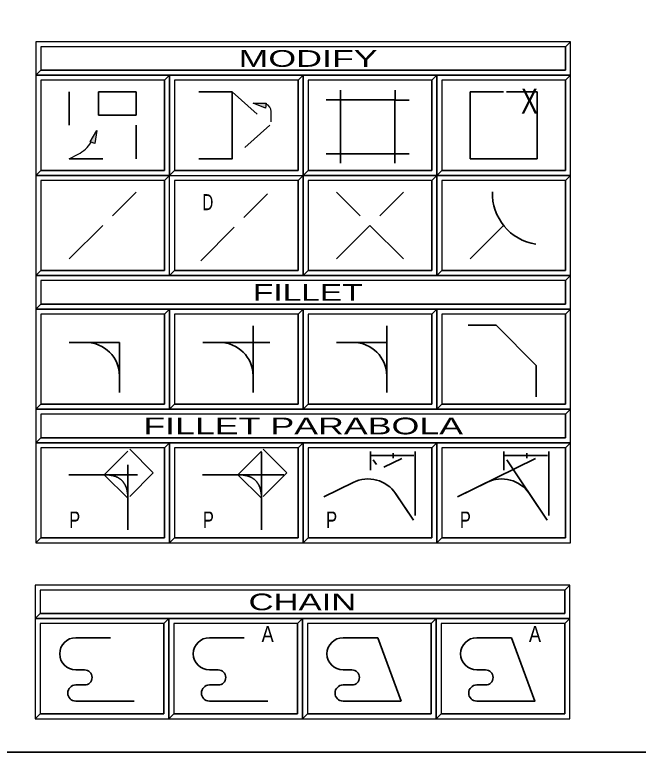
# Model space of a CAD drawing. Extents: x 95906.8 to 95923.6, y 90964.8 to 90972.8.
# Drawn here: x 95908.871 to 95910.737, y 90964.762 to 90966.969 of the extents above; entities that cross this region are included whole.
import ezdxf
from ezdxf.enums import TextEntityAlignment as Align

# ---------------------------------------------------------------- set-up
doc = ezdxf.new("R2010")
doc.units = 0
doc.header["$LTSCALE"] = 0.019
doc.linetypes.add('DOTTED', pattern=[1.5, 0.3, -1.2])
doc.linetypes.add('MEDIUM_DASHED', pattern=[4.5, 3, -1.5])
for name, color, linetype, lineweight in [('1', 7, 'Continuous', 25), ('11', 7, 'Continuous', 25), ('12', 7, 'Continuous', 25), ('18', 7, 'Continuous', 25), ('2', 7, 'Continuous', 13), ('3', 7, 'Continuous', 25), ('6', 7, 'Continuous', 35), ('7', 7, 'Continuous', 35)]:
    doc.layers.add(name, color=color, linetype=linetype, lineweight=lineweight)

msp = doc.modelspace()

# ---------------------------------------------------------------- hatches: boundary and pattern name
at = {"layer": '6'}
for points in [[(95909.5847, 90966.7042), (95909.6243, 90966.7047), (95909.6217, 90966.6895)], [(95909.1174, 90966.6228), (95909.1115, 90966.5841), (95909.097, 90966.5893)]]:
    msp.add_hatch(color=256, dxfattribs=at).paths.add_polyline_path(points)

# ---------------------------------------------------------------- linework, layer by layer
at = {"layer": '1'}
for points in [[(95908.9345, 90966.7883), (95910.5345, 90966.7883), (95910.5345, 90966.8883), (95908.9345, 90966.8883)], [(95908.9345, 90966.4883), (95909.3345, 90966.4883), (95909.3345, 90966.7883), (95908.9345, 90966.7883)], [(95909.3345, 90966.4883), (95909.7345, 90966.4883), (95909.7345, 90966.7883), (95909.3345, 90966.7883)], [(95909.7345, 90966.4883), (95910.1345, 90966.4883), (95910.1345, 90966.7883), (95909.7345, 90966.7883)], [(95910.1345, 90966.4883), (95910.5345, 90966.4883), (95910.5345, 90966.7883), (95910.1345, 90966.7883)], [(95908.9345, 90966.1883), (95909.3345, 90966.1883), (95909.3345, 90966.4883), (95908.9345, 90966.4883)], [(95909.7345, 90966.1883), (95910.1345, 90966.1883), (95910.1345, 90966.4883), (95909.7345, 90966.4883)], [(95910.1345, 90966.1883), (95910.5345, 90966.1883), (95910.5345, 90966.4883), (95910.1345, 90966.4883)], [(95908.9345, 90966.0883), (95910.5345, 90966.0883), (95910.5345, 90966.1883), (95908.9345, 90966.1883)], [(95908.9345, 90965.7883), (95909.3345, 90965.7883), (95909.3345, 90966.0883), (95908.9345, 90966.0883)], [(95909.3345, 90965.7883), (95909.7345, 90965.7883), (95909.7345, 90966.0883), (95909.3345, 90966.0883)], [(95909.7345, 90965.7883), (95910.1345, 90965.7883), (95910.1345, 90966.0883), (95909.7345, 90966.0883)], [(95910.1345, 90965.7883), (95910.5345, 90965.7883), (95910.5345, 90966.0883), (95910.1345, 90966.0883)], [(95908.9345, 90965.6883), (95910.5345, 90965.6883), (95910.5345, 90965.7883), (95908.9345, 90965.7883)], [(95908.9345, 90965.3883), (95909.3345, 90965.3883), (95909.3345, 90965.6883), (95908.9345, 90965.6883)], [(95909.3345, 90965.3883), (95909.7345, 90965.3883), (95909.7345, 90965.6883), (95909.3345, 90965.6883)], [(95909.7345, 90965.3883), (95910.1345, 90965.3883), (95910.1345, 90965.6883), (95909.7345, 90965.6883)], [(95910.1345, 90965.3883), (95910.5345, 90965.3883), (95910.5345, 90965.6883), (95910.1345, 90965.6883)], [(95908.9323, 90965.1617), (95910.5323, 90965.1617), (95910.5323, 90965.2617), (95908.9323, 90965.2617)], [(95908.9323, 90964.8617), (95909.3323, 90964.8617), (95909.3323, 90965.1617), (95908.9323, 90965.1617)], [(95909.3323, 90964.8617), (95909.7323, 90964.8617), (95909.7323, 90965.1617), (95909.3323, 90965.1617)], [(95909.7323, 90964.8617), (95910.1323, 90964.8617), (95910.1323, 90965.1617), (95909.7323, 90965.1617)], [(95910.1323, 90964.8617), (95910.5323, 90964.8617), (95910.5323, 90965.1617), (95910.1323, 90965.1617)]]:
    msp.add_lwpolyline(points, close=True, dxfattribs=at)
at = {"layer": '11'}
for points in [[(95909.3495, 90966.5033), (95909.7195, 90966.5033), (95909.7195, 90966.7733), (95909.3495, 90966.7733)], [(95909.7495, 90966.5033), (95910.1195, 90966.5033), (95910.1195, 90966.7733), (95909.7495, 90966.7733)], [(95910.1495, 90966.5033), (95910.5195, 90966.5033), (95910.5195, 90966.7733), (95910.1495, 90966.7733)], [(95909.3495, 90966.2033), (95909.7195, 90966.2033), (95909.7195, 90966.4733), (95909.3495, 90966.4733)], [(95909.7495, 90966.2033), (95910.1195, 90966.2033), (95910.1195, 90966.4733), (95909.7495, 90966.4733)], [(95910.1495, 90966.2033), (95910.5195, 90966.2033), (95910.5195, 90966.4733), (95910.1495, 90966.4733)], [(95909.3495, 90965.8033), (95909.7195, 90965.8033), (95909.7195, 90966.0733), (95909.3495, 90966.0733)], [(95909.7495, 90965.8033), (95910.1195, 90965.8033), (95910.1195, 90966.0733), (95909.7495, 90966.0733)], [(95910.1495, 90965.8033), (95910.5195, 90965.8033), (95910.5195, 90966.0733), (95910.1495, 90966.0733)], [(95908.9495, 90965.4033), (95909.3195, 90965.4033), (95909.3195, 90965.6733), (95908.9495, 90965.6733)], [(95909.3495, 90965.4033), (95909.7195, 90965.4033), (95909.7195, 90965.6733), (95909.3495, 90965.6733)], [(95909.7495, 90965.4033), (95910.1195, 90965.4033), (95910.1195, 90965.6733), (95909.7495, 90965.6733)], [(95910.1495, 90965.4033), (95910.5195, 90965.4033), (95910.5195, 90965.6733), (95910.1495, 90965.6733)], [(95909.3473, 90964.8767), (95909.7173, 90964.8767), (95909.7173, 90965.1467), (95909.3473, 90965.1467)], [(95909.7473, 90964.8767), (95910.1173, 90964.8767), (95910.1173, 90965.1467), (95909.7473, 90965.1467)], [(95910.1473, 90964.8767), (95910.5173, 90964.8767), (95910.5173, 90965.1467), (95910.1473, 90965.1467)]]:
    msp.add_lwpolyline(points, close=True, dxfattribs=at)
at = {"layer": '12'}
for points in [[(95908.9495, 90966.5033), (95909.3195, 90966.5033), (95909.3195, 90966.7733), (95908.9495, 90966.7733)], [(95908.9495, 90966.2033), (95909.3195, 90966.2033), (95909.3195, 90966.4733), (95908.9495, 90966.4733)], [(95908.9495, 90965.8033), (95909.3195, 90965.8033), (95909.3195, 90966.0733), (95908.9495, 90966.0733)], [(95908.9473, 90964.8767), (95909.3173, 90964.8767), (95909.3173, 90965.1467), (95908.9473, 90965.1467)]]:
    msp.add_lwpolyline(points, close=True, dxfattribs=at)
at = {"layer": '18'}
for points in [[(95908.9495, 90966.8033), (95910.5195, 90966.8033), (95910.5195, 90966.8733), (95908.9495, 90966.8733)], [(95908.9495, 90966.1033), (95910.5195, 90966.1033), (95910.5195, 90966.1733), (95908.9495, 90966.1733)], [(95908.9495, 90965.7033), (95910.5195, 90965.7033), (95910.5195, 90965.7733), (95908.9495, 90965.7733)], [(95908.9473, 90965.1767), (95910.5173, 90965.1767), (95910.5173, 90965.2467), (95908.9473, 90965.2467)]]:
    msp.add_lwpolyline(points, close=True, dxfattribs=at)
at = {"layer": '2'}
for points in [[(95908.9345, 90966.8883), (95908.9345, 90966.7883), (95908.9495, 90966.8033), (95908.9495, 90966.8733), (95910.5195, 90966.8733), (95910.5345, 90966.8883)], [(95908.9345, 90966.7883), (95908.9345, 90966.4883), (95908.9495, 90966.5033), (95908.9495, 90966.7733), (95909.3195, 90966.7733), (95909.3345, 90966.7883)], [(95909.3345, 90966.7883), (95909.3345, 90966.4883), (95909.3495, 90966.5033), (95909.3495, 90966.7733), (95909.7195, 90966.7733), (95909.7345, 90966.7883)], [(95909.7345, 90966.7883), (95909.7345, 90966.4883), (95909.7495, 90966.5033), (95909.7495, 90966.7733), (95910.1195, 90966.7733), (95910.1345, 90966.7883)], [(95910.1345, 90966.7883), (95910.1345, 90966.4883), (95910.1495, 90966.5033), (95910.1495, 90966.7733), (95910.5195, 90966.7733), (95910.5345, 90966.7883)], [(95908.9345, 90966.4883), (95908.9345, 90966.1883), (95908.9495, 90966.2033), (95908.9495, 90966.4733), (95909.3195, 90966.4733), (95909.3345, 90966.4883)], [(95909.3345, 90966.4883), (95909.3345, 90966.1883), (95909.3495, 90966.2033), (95909.3495, 90966.4733), (95909.7195, 90966.4733), (95909.7345, 90966.4883)], [(95909.7345, 90966.4883), (95909.7345, 90966.1883), (95909.7495, 90966.2033), (95909.7495, 90966.4733), (95910.1195, 90966.4733), (95910.1345, 90966.4883)], [(95910.1345, 90966.4883), (95910.1345, 90966.1883), (95910.1495, 90966.2033), (95910.1495, 90966.4733), (95910.5195, 90966.4733), (95910.5345, 90966.4883)], [(95908.9345, 90966.1883), (95908.9345, 90966.0883), (95908.9495, 90966.1033), (95908.9495, 90966.1733), (95910.5195, 90966.1733), (95910.5345, 90966.1883)], [(95908.9345, 90966.0883), (95908.9345, 90965.7883), (95908.9495, 90965.8033), (95908.9495, 90966.0733), (95909.3195, 90966.0733), (95909.3345, 90966.0883)], [(95909.3345, 90966.0883), (95909.3345, 90965.7883), (95909.3495, 90965.8033), (95909.3495, 90966.0733), (95909.7195, 90966.0733), (95909.7345, 90966.0883)], [(95909.7345, 90966.0883), (95909.7345, 90965.7883), (95909.7495, 90965.8033), (95909.7495, 90966.0733), (95910.1195, 90966.0733), (95910.1345, 90966.0883)], [(95910.1345, 90966.0883), (95910.1345, 90965.7883), (95910.1495, 90965.8033), (95910.1495, 90966.0733), (95910.5195, 90966.0733), (95910.5345, 90966.0883)], [(95908.9345, 90965.7883), (95908.9345, 90965.6883), (95908.9495, 90965.7033), (95908.9495, 90965.7733), (95910.5195, 90965.7733), (95910.5345, 90965.7883)], [(95908.9345, 90965.6883), (95908.9345, 90965.3883), (95908.9495, 90965.4033), (95908.9495, 90965.6733), (95909.3195, 90965.6733), (95909.3345, 90965.6883)], [(95909.3345, 90965.6883), (95909.3345, 90965.3883), (95909.3495, 90965.4033), (95909.3495, 90965.6733), (95909.7195, 90965.6733), (95909.7345, 90965.6883)], [(95909.7345, 90965.6883), (95909.7345, 90965.3883), (95909.7495, 90965.4033), (95909.7495, 90965.6733), (95910.1195, 90965.6733), (95910.1345, 90965.6883)], [(95910.1345, 90965.6883), (95910.1345, 90965.3883), (95910.1495, 90965.4033), (95910.1495, 90965.6733), (95910.5195, 90965.6733), (95910.5345, 90965.6883)], [(95908.9323, 90965.2617), (95908.9323, 90965.1617), (95908.9473, 90965.1767), (95908.9473, 90965.2467), (95910.5173, 90965.2467), (95910.5323, 90965.2617)], [(95908.9323, 90965.1617), (95908.9323, 90964.8617), (95908.9473, 90964.8767), (95908.9473, 90965.1467), (95909.3173, 90965.1467), (95909.3323, 90965.1617)], [(95909.3323, 90965.1617), (95909.3323, 90964.8617), (95909.3473, 90964.8767), (95909.3473, 90965.1467), (95909.7173, 90965.1467), (95909.7323, 90965.1617)], [(95909.7323, 90965.1617), (95909.7323, 90964.8617), (95909.7473, 90964.8767), (95909.7473, 90965.1467), (95910.1173, 90965.1467), (95910.1323, 90965.1617)], [(95910.1323, 90965.1617), (95910.1323, 90964.8617), (95910.1473, 90964.8767), (95910.1473, 90965.1467), (95910.5173, 90965.1467), (95910.5323, 90965.1617)]]:
    msp.add_lwpolyline(points, close=True, dxfattribs=at)
at = {"layer": '3'}
for points in [[(95908.9345, 90966.7883), (95910.5345, 90966.7883), (95910.5345, 90966.8883), (95910.5195, 90966.8733), (95910.5195, 90966.8033), (95908.9495, 90966.8033)], [(95908.9345, 90966.4883), (95909.3345, 90966.4883), (95909.3345, 90966.7883), (95909.3195, 90966.7733), (95909.3195, 90966.5033), (95908.9495, 90966.5033)], [(95909.3345, 90966.4883), (95909.7345, 90966.4883), (95909.7345, 90966.7883), (95909.7195, 90966.7733), (95909.7195, 90966.5033), (95909.3495, 90966.5033)], [(95909.7345, 90966.4883), (95910.1345, 90966.4883), (95910.1345, 90966.7883), (95910.1195, 90966.7733), (95910.1195, 90966.5033), (95909.7495, 90966.5033)], [(95910.1345, 90966.4883), (95910.5345, 90966.4883), (95910.5345, 90966.7883), (95910.5195, 90966.7733), (95910.5195, 90966.5033), (95910.1495, 90966.5033)], [(95908.9345, 90966.1883), (95909.3345, 90966.1883), (95909.3345, 90966.4883), (95909.3195, 90966.4733), (95909.3195, 90966.2033), (95908.9495, 90966.2033)], [(95909.3345, 90966.1883), (95909.7345, 90966.1883), (95909.7345, 90966.4883), (95909.7195, 90966.4733), (95909.7195, 90966.2033), (95909.3495, 90966.2033)], [(95909.7345, 90966.1883), (95910.1345, 90966.1883), (95910.1345, 90966.4883), (95910.1195, 90966.4733), (95910.1195, 90966.2033), (95909.7495, 90966.2033)], [(95910.1345, 90966.1883), (95910.5345, 90966.1883), (95910.5345, 90966.4883), (95910.5195, 90966.4733), (95910.5195, 90966.2033), (95910.1495, 90966.2033)], [(95908.9345, 90966.0883), (95910.5345, 90966.0883), (95910.5345, 90966.1883), (95910.5195, 90966.1733), (95910.5195, 90966.1033), (95908.9495, 90966.1033)], [(95908.9345, 90965.7883), (95909.3345, 90965.7883), (95909.3345, 90966.0883), (95909.3195, 90966.0733), (95909.3195, 90965.8033), (95908.9495, 90965.8033)], [(95909.3345, 90965.7883), (95909.7345, 90965.7883), (95909.7345, 90966.0883), (95909.7195, 90966.0733), (95909.7195, 90965.8033), (95909.3495, 90965.8033)], [(95909.7345, 90965.7883), (95910.1345, 90965.7883), (95910.1345, 90966.0883), (95910.1195, 90966.0733), (95910.1195, 90965.8033), (95909.7495, 90965.8033)], [(95910.1345, 90965.7883), (95910.5345, 90965.7883), (95910.5345, 90966.0883), (95910.5195, 90966.0733), (95910.5195, 90965.8033), (95910.1495, 90965.8033)], [(95908.9345, 90965.6883), (95910.5345, 90965.6883), (95910.5345, 90965.7883), (95910.5195, 90965.7733), (95910.5195, 90965.7033), (95908.9495, 90965.7033)], [(95908.9345, 90965.3883), (95909.3345, 90965.3883), (95909.3345, 90965.6883), (95909.3195, 90965.6733), (95909.3195, 90965.4033), (95908.9495, 90965.4033)], [(95909.3345, 90965.3883), (95909.7345, 90965.3883), (95909.7345, 90965.6883), (95909.7195, 90965.6733), (95909.7195, 90965.4033), (95909.3495, 90965.4033)], [(95909.7345, 90965.3883), (95910.1345, 90965.3883), (95910.1345, 90965.6883), (95910.1195, 90965.6733), (95910.1195, 90965.4033), (95909.7495, 90965.4033)], [(95910.1345, 90965.3883), (95910.5345, 90965.3883), (95910.5345, 90965.6883), (95910.5195, 90965.6733), (95910.5195, 90965.4033), (95910.1495, 90965.4033)], [(95908.9323, 90965.1617), (95910.5323, 90965.1617), (95910.5323, 90965.2617), (95910.5173, 90965.2467), (95910.5173, 90965.1767), (95908.9473, 90965.1767)], [(95908.9323, 90964.8617), (95909.3323, 90964.8617), (95909.3323, 90965.1617), (95909.3173, 90965.1467), (95909.3173, 90964.8767), (95908.9473, 90964.8767)], [(95909.3323, 90964.8617), (95909.7323, 90964.8617), (95909.7323, 90965.1617), (95909.7173, 90965.1467), (95909.7173, 90964.8767), (95909.3473, 90964.8767)], [(95909.7323, 90964.8617), (95910.1323, 90964.8617), (95910.1323, 90965.1617), (95910.1173, 90965.1467), (95910.1173, 90964.8767), (95909.7473, 90964.8767)], [(95910.1323, 90964.8617), (95910.5323, 90964.8617), (95910.5323, 90965.1617), (95910.5173, 90965.1467), (95910.5173, 90964.8767), (95910.1473, 90964.8767)]]:
    msp.add_lwpolyline(points, close=True, dxfattribs=at)
at = {"layer": '6', "linetype": 'MEDIUM_DASHED'}
for p, q in [((95909.8466, 90966.715), (95909.8466, 90966.7434)), ((95910.0094, 90966.715), (95910.0094, 90966.7434)), ((95909.8032, 90966.715), (95909.8466, 90966.715)), ((95910.0086, 90966.7133), (95910.052, 90966.7133)), ((95909.8032, 90966.553), (95909.8466, 90966.553)), ((95909.8466, 90966.5246), (95909.8466, 90966.553)), ((95910.0086, 90966.553), (95910.052, 90966.553)), ((95910.0086, 90966.5246), (95910.0086, 90966.553)), ((95909.2345, 90966.4383), (95909.1345, 90966.3383)), ((95909.6278, 90966.4329), (95909.5278, 90966.3329)), ((95909.8345, 90966.4383), (95909.9345, 90966.3383)), ((95910.0345, 90966.4383), (95909.9345, 90966.3383)), ((95910.3345, 90966.3383), (95910.2845, 90966.2883)), ((95909.1845, 90965.8883), (95909.1845, 90966.0383)), ((95909.0845, 90965.9883), (95909.2345, 90965.9883)), ((95909.8845, 90965.9883), (95910.0345, 90965.9883))]:
    msp.add_line(p, q, dxfattribs=at)
at = {"layer": '6', "lineweight": 25}
for p, q in [((95909.6385, 90966.6489), (95909.6385, 90966.6792)), ((95909.0345, 90966.5383), (95909.0609, 90966.5518))]:
    msp.add_line(p, q, dxfattribs=at)
at = {"layer": '6'}
for p, q in [((95909.0345, 90966.2383), (95909.1345, 90966.3383)), ((95909.4278, 90966.2329), (95909.5278, 90966.3329)), ((95909.8345, 90966.2383), (95909.9345, 90966.3383)), ((95910.0345, 90966.2383), (95909.9345, 90966.3383)), ((95910.2345, 90966.2383), (95910.2845, 90966.2883)), ((95909.5845, 90965.8383), (95909.5845, 90966.0383)), ((95909.9845, 90965.8883), (95909.9845, 90966.0383)), ((95909.0345, 90965.9883), (95909.0845, 90965.9883)), ((95909.4345, 90965.9883), (95909.6345, 90965.9883)), ((95909.8345, 90965.9883), (95909.8845, 90965.9883)), ((95909.1845, 90965.8383), (95909.1845, 90965.8883)), ((95909.9845, 90965.8383), (95909.9845, 90965.8883)), ((95909.6099, 90965.5218), (95909.6099, 90965.6601)), ((95909.9339, 90965.6503), (95910.0662, 90965.6503)), ((95909.9356, 90965.6062), (95909.9356, 90965.6617)), ((95910.0041, 90965.6421), (95910.0041, 90965.6568)), ((95910.0694, 90965.4707), (95910.0694, 90965.6617)), ((95910.3339, 90965.6503), (95910.4662, 90965.6503)), ((95910.3356, 90965.6062), (95910.3356, 90965.6617)), ((95910.4041, 90965.6421), (95910.4041, 90965.6568)), ((95910.4694, 90965.4707), (95910.4694, 90965.6617)), ((95910.1968, 90965.5262), (95910.43, 90965.6413)), ((95910.4645, 90965.4561), (95910.3444, 90965.6366)), ((95909.0328, 90965.5925), (95909.1392, 90965.5925)), ((95909.4328, 90965.5925), (95909.5392, 90965.5925)), ((95909.5392, 90965.5925), (95909.6768, 90965.5925)), ((95909.7968, 90965.5262), (95909.8843, 90965.5694)), ((95910.1968, 90965.5262), (95910.2843, 90965.5694)), ((95910.0645, 90965.4561), (95910.0118, 90965.5353)), ((95910.4645, 90965.4561), (95910.4118, 90965.5353)), ((95909.2099, 90965.4276), (95909.2099, 90965.5218)), ((95909.6099, 90965.4276), (95909.6099, 90965.5218)), ((95909.1582, 90965.1045), (95909.054, 90965.1045)), ((95909.5582, 90965.1045), (95909.454, 90965.1045)), ((95909.9582, 90965.1045), (95909.854, 90965.1045)), ((95909.9582, 90965.1045), (95910.0283, 90964.9148)), ((95910.3582, 90965.1045), (95910.254, 90965.1045)), ((95909.054, 90965.0081), (95909.0804, 90965.0081)), ((95909.454, 90965.0081), (95909.4804, 90965.0081)), ((95909.854, 90965.0081), (95909.8804, 90965.0081)), ((95910.254, 90965.0081), (95910.2804, 90965.0081)), ((95909.0804, 90964.963), (95909.054, 90964.963)), ((95909.4804, 90964.963), (95909.454, 90964.963)), ((95909.8804, 90964.963), (95909.854, 90964.963)), ((95910.2804, 90964.963), (95910.254, 90964.963)), ((95909.054, 90964.9148), (95909.2283, 90964.9148)), ((95909.454, 90964.9148), (95909.6283, 90964.9148)), ((95909.854, 90964.9148), (95910.0283, 90964.9148))]:
    msp.add_line(p, q, dxfattribs=at)
at = {"layer": '6', "linetype": 'DOTTED'}
for p, q in [((95909.2099, 90965.5218), (95909.2099, 90965.6601)), ((95909.7968, 90965.5262), (95910.03, 90965.6413)), ((95910.0645, 90965.4561), (95909.9444, 90965.6366)), ((95909.1392, 90965.5925), (95909.2768, 90965.5925))]:
    msp.add_line(p, q, dxfattribs=at)
at = {"layer": '6', "linetype": 'MEDIUM_DASHED'}
msp.add_lwpolyline([(95909.2345, 90966.7383), (95909.0345, 90966.7383), (95909.0345, 90966.5383), (95909.2345, 90966.5383)], close=True, dxfattribs=at)
at = {"layer": '6'}
msp.add_lwpolyline([(95909.2345, 90966.7383), (95909.1223, 90966.7383), (95909.1223, 90966.6691), (95909.2345, 90966.6691)], close=True, dxfattribs=at)
for points in [[(95909.4222, 90966.7383), (95909.5223, 90966.7383), (95909.5223, 90966.5383), (95909.4224, 90966.5383)], [(95910.3346, 90966.7383), (95910.2345, 90966.7383), (95910.2345, 90966.5383), (95910.4345, 90966.5383), (95910.4345, 90966.6383)], [(95910.0094, 90966.715), (95909.8466, 90966.715), (95909.8466, 90966.553), (95910.0086, 90966.553), (95910.0086, 90966.7133)], [(95910.2279, 90966.0397), (95910.3118, 90966.0397), (95910.4318, 90965.9197), (95910.4318, 90965.8258)], [(95910.254, 90964.9148), (95910.4283, 90964.9148), (95910.3582, 90965.1045)]]:
    msp.add_lwpolyline(points, dxfattribs=at)
at = {"layer": '6', "linetype": 'MEDIUM_DASHED'}
for points in [[(95909.5223, 90966.7383), (95909.6345, 90966.6383), (95909.5223, 90966.5383)], [(95910.3427, 90966.7383), (95910.4345, 90966.7383), (95910.4345, 90966.6383)]]:
    msp.add_lwpolyline(points, dxfattribs=at)
at = {"layer": '6', "lineweight": 25}
for points in [[(95909.5847, 90966.7042), (95909.6243, 90966.7047), (95909.6217, 90966.6895)], [(95909.1174, 90966.6228), (95909.1115, 90966.5841), (95909.097, 90966.5893)]]:
    msp.add_lwpolyline(points, close=True, dxfattribs=at)
at = {"layer": '6', "linetype": 'DOTTED'}
for points in [[(95909.2099, 90965.5218), (95909.1392, 90965.5925), (95909.2153, 90965.6686), (95909.286, 90965.5979)], [(95909.6099, 90965.5218), (95909.5392, 90965.5925), (95909.6153, 90965.6686), (95909.686, 90965.5979)]]:
    msp.add_lwpolyline(points, close=True, dxfattribs=at)
at = {"layer": '6', "lineweight": 25}
for centre, radius, start, end in [((95909.6135, 90966.6792), 0.025, 0, 67.0459), ((95909.0153, 90966.6408), 0.1, 297.1547, 327.7877)]:
    msp.add_arc(centre, radius, start, end, dxfattribs=at)
at = {"layer": '6'}
for centre, radius, start, end in [((95910.4553, 90966.4345), 0.1544, 178.1343, 260.7711), ((95909.0845, 90965.8883), 0.1, 0, 90), ((95909.4845, 90965.8883), 0.1, 0, 90), ((95909.8845, 90965.8883), 0.1, 0, 90), ((95909.9286, 90965.4798), 0.1, 33.7228, 116.3032), ((95910.3286, 90965.4798), 0.1, 33.7228, 116.3032), ((95909.054, 90965.0563), 0.0482, 90, 270), ((95909.454, 90965.0563), 0.0482, 90, 270), ((95909.854, 90965.0563), 0.0482, 90, 270), ((95910.254, 90965.0563), 0.0482, 90, 270), ((95909.0804, 90964.9856), 0.0226, 270, 90), ((95909.4804, 90964.9856), 0.0226, 270, 90), ((95909.8804, 90964.9856), 0.0226, 270, 90), ((95910.2804, 90964.9856), 0.0226, 270, 90), ((95909.054, 90964.9389), 0.0241, 90, 270), ((95909.454, 90964.9389), 0.0241, 90, 270), ((95909.854, 90964.9389), 0.0241, 90, 270), ((95910.254, 90964.9389), 0.0241, 90, 270)]:
    msp.add_arc(centre, radius, start, end, dxfattribs=at)
for points in [[(95909.2099, 90965.5218), (95909.2099, 90965.5251), (95909.2097, 90965.5284), (95909.2095, 90965.5315), (95909.2093, 90965.5346), (95909.2089, 90965.5376), (95909.2085, 90965.5405), (95909.2079, 90965.5434), (95909.2073, 90965.5462), (95909.2067, 90965.5488), (95909.2059, 90965.5515), (95909.205, 90965.554), (95909.2041, 90965.5564), (95909.2031, 90965.5588), (95909.202, 90965.5611), (95909.2009, 90965.5633), (95909.1996, 90965.5654), (95909.1983, 90965.5674), (95909.1969, 90965.5694), (95909.1954, 90965.5713), (95909.1939, 90965.5731), (95909.1922, 90965.5748), (95909.1905, 90965.5765), (95909.1887, 90965.578), (95909.1868, 90965.5795), (95909.1848, 90965.5809), (95909.1828, 90965.5822), (95909.1807, 90965.5835), (95909.1785, 90965.5846), (95909.1762, 90965.5857), (95909.1738, 90965.5867), (95909.1714, 90965.5876), (95909.1689, 90965.5885), (95909.1662, 90965.5893), (95909.1636, 90965.5899), (95909.1608, 90965.5905), (95909.1579, 90965.5911), (95909.155, 90965.5915), (95909.152, 90965.5919), (95909.1489, 90965.5921), (95909.1458, 90965.5923), (95909.1425, 90965.5925), (95909.1392, 90965.5925)], [(95909.6099, 90965.5218), (95909.6099, 90965.5251), (95909.6097, 90965.5284), (95909.6095, 90965.5315), (95909.6093, 90965.5346), (95909.6089, 90965.5376), (95909.6085, 90965.5405), (95909.6079, 90965.5434), (95909.6073, 90965.5462), (95909.6067, 90965.5488), (95909.6059, 90965.5515), (95909.605, 90965.554), (95909.6041, 90965.5564), (95909.6031, 90965.5588), (95909.602, 90965.5611), (95909.6009, 90965.5633), (95909.5996, 90965.5654), (95909.5983, 90965.5674), (95909.5969, 90965.5694), (95909.5954, 90965.5713), (95909.5939, 90965.5731), (95909.5922, 90965.5748), (95909.5905, 90965.5765), (95909.5887, 90965.578), (95909.5868, 90965.5795), (95909.5848, 90965.5809), (95909.5828, 90965.5822), (95909.5807, 90965.5835), (95909.5785, 90965.5846), (95909.5762, 90965.5857), (95909.5738, 90965.5867), (95909.5714, 90965.5876), (95909.5689, 90965.5885), (95909.5662, 90965.5893), (95909.5636, 90965.5899), (95909.5608, 90965.5905), (95909.5579, 90965.5911), (95909.555, 90965.5915), (95909.552, 90965.5919), (95909.5489, 90965.5921), (95909.5458, 90965.5923), (95909.5425, 90965.5925), (95909.5392, 90965.5925)]]:
    msp.add_spline(points, degree=3, dxfattribs=at)
at = {"layer": '7'}
msp.add_lwpolyline([(95906.8323, 90972.7617), (95918.8323, 90972.7617), (95918.8323, 90964.7617), (95906.8323, 90964.7617)], close=True, dxfattribs=at)

# ---------------------------------------------------------------- texts
at = {"layer": '6'}
for s, height, width, p in [('X', 0.0752, 0.75, (95910.4117, 90966.6728)), ('D', 0.048, 0.7, (95909.4493, 90966.3842)), ('P', 0.0491, 0.75, (95909.0507, 90965.4331)), ('P', 0.0491, 0.75, (95909.4508, 90965.4331)), ('P', 0.0491, 0.75, (95909.8197, 90965.4331)), ('P', 0.0491, 0.75, (95910.2199, 90965.4331)), ('A', 0.048, 0.85, (95909.6283, 90965.0914)), ('A', 0.048, 0.85, (95910.4284, 90965.0914))]:
    msp.add_text(s, height=height, dxfattribs=dict(at, width=width)).set_placement(p, align=Align.CENTER)
at = {"layer": '7'}
for s, width, p in [('         MODIFY        ', 1.6, (95909.7344, 90966.8133)), ('         FILLET        ', 1.5, (95909.7345, 90966.1133)), ('    FILLET PARABOLA    ', 1.6, (95909.7345, 90965.7133)), ('         CHAIN         ', 1.55, (95909.7323, 90965.1867))]:
    msp.add_text(s, height=0.04999, dxfattribs=dict(at, width=width)).set_placement(p, align=Align.CENTER)

doc.saveas('drawing.dxf')
